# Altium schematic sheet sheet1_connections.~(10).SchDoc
size A4; SheetNumber: 1; SheetTotal: 3
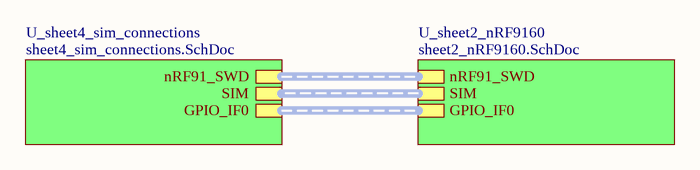
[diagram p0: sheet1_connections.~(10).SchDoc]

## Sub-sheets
U_sheet2_nRF9160 = sheet2_nRF9160.SchDoc: nRF91_SWD (harness SWD), SIM (harness SIM), GPIO_IF0 (harness GPIO_IF0)
U_sheet4_sim_connections = sheet4_sim_connections.SchDoc: nRF91_SWD (harness SWD), GPIO_IF0 (harness GPIO_IF0), SIM (harness SIM)

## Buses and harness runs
harness sheet U_sheet2_nRF9160/GPIO_IF0 = sheet U_sheet4_sim_connections/GPIO_IF0
harness sheet U_sheet2_nRF9160/nRF91_SWD = sheet U_sheet4_sim_connections/nRF91_SWD
harness sheet U_sheet2_nRF9160/SIM = sheet U_sheet4_sim_connections/SIM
